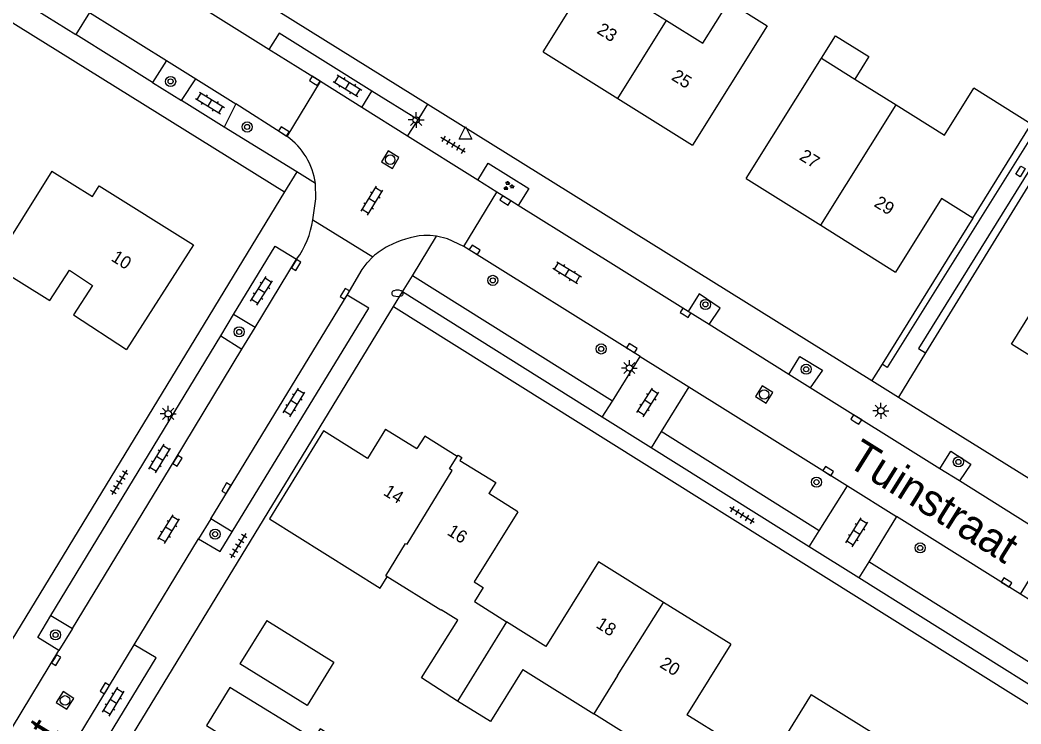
# Model space of a CAD drawing. Extents: x 136000 to 141014, y 402000 to 403500.
# Drawn here: x 137879.3 to 137958.3, y 402207.2 to 402262.7 of the extents above; entities that cross this region are included whole.
import ezdxf

# ---------------------------------------------------------------- set-up
doc = ezdxf.new("R2010")
doc.units = 0
for name, color, linetype in [('gg-afsc-erfafscheiding', 7, 'Continuous'), ('gg-anno-huisnummerreeks BGT', 7, 'Continuous'), ('gg-anno-openbare ruimte label', 7, 'Continuous'), ('gg-bbg-bijgebouw', 7, 'Continuous'), ('gg-bbg-gedigitaliseerde bebouwing', 7, 'Continuous'), ('gg-bbg-gedigitaliseerde bijgebouw', 7, 'Continuous'), ('gg-bbg-hoofdgebouw', 7, 'Continuous'), ('gg-bbg-luifel en loopbrug', 7, 'Continuous'), ('gg-bbg-tussenscheiding', 7, 'Continuous'), ('gg-knt-verharding', 7, 'Continuous'), ('gg-knt-verharding nz', 7, 'Continuous'), ('gt-grn-groengrens', 7, 'Continuous'), ('gt-grn-vlakafsluiter', 7, 'Continuous'), ('gt-grn-weggrens', 7, 'Continuous'), ('gt-symb-boom', 7, 'Continuous'), ('gt-symb-brandkraan', 7, 'Continuous'), ('gt-symb-groenvak', 7, 'Continuous'), ('gt-symb-klinker verharding', 7, 'Continuous'), ('gt-symb-kolk', 7, 'Continuous'), ('gt-symb-kolk center center', 7, 'Continuous'), ('gt-symb-lichtmast', 7, 'Continuous'), ('gt-symb-rioolschacht', 7, 'Continuous'), ('gt-symb-tegel verharding', 7, 'Continuous'), ('gt-symb-waterafsluiter', 7, 'Continuous')]:
    doc.layers.add(name, color=color, linetype=linetype)

# ---------------------------------------------------------------- blocks, each defined once
blk = doc.blocks.new('gt0-KOLKCC')
at = {"layer": 'gt-symb-kolk center center'}
blk.add_lwpolyline([(-0.375, 0.2), (0.375, 0.2), (0.375, -0.2), (-0.375, -0.2)], close=True, dxfattribs=at)
blk = doc.blocks.new('gt0-BOOM')
at = {"layer": 'gt-symb-boom'}
for radius in [0.4, 0.2]:
    blk.add_circle((0, 0), radius, dxfattribs=at)
blk = doc.blocks.new('gt0-KOLK')
at = {"layer": 'gt-symb-kolk'}
blk.add_lwpolyline([(0, 0), (0.375, 0), (0.375, 0.4), (-0.375, 0.4), (-0.375, 0), (0, 0)], dxfattribs=at)
blk = doc.blocks.new('gt0-KL1')
at = {"layer": 'gt-symb-klinker verharding'}
for p, q in [((-1.15, 0.3), (1.15, 0.3)), ((-1, -0.3), (-1, 0.3)), ((-0.5, 0.3), (-0.5, 0.45)), ((0, -0.3), (0, 0.3)), ((0.5, 0.3), (0.5, 0.45)), ((1, -0.3), (1, 0.3)), ((-1.15, -0.3), (1.15, -0.3)), ((-0.5, -0.45), (-0.5, -0.3)), ((0.5, -0.45), (0.5, -0.3))]:
    blk.add_line(p, q, dxfattribs=at)
blk = doc.blocks.new('gt0-LMAST')
at = {"layer": 'gt-symb-lichtmast'}
for p, q in [((-0.182, 0.173), (-0.447, 0.438)), ((-0.005, 0.246), (-0.005, 0.621)), ((0.172, 0.173), (0.437, 0.438)), ((-0.255, -0.004), (-0.63, -0.004)), ((-0.182, -0.181), (-0.447, -0.446)), ((-0.005, -0.254), (-0.005, -0.629)), ((0.437, -0.446), (0.172, -0.181)), ((0.245, -0.004), (0.62, -0.004))]:
    blk.add_line(p, q, dxfattribs=at)
blk.add_circle((-0.005, -0.004), 0.25, dxfattribs=at)
blk = doc.blocks.new('gt0-RS')
at = {"layer": 'gt-symb-rioolschacht'}
blk.add_lwpolyline([(-0.5, -0.5), (0.5, -0.5), (0.5, 0.5), (-0.5, 0.5)], close=True, dxfattribs=at)
blk.add_circle((0, 0), 0.375, dxfattribs=at)
blk = doc.blocks.new('gt0-GRVAK')
at = {"layer": 'gt-symb-groenvak'}
for p, q in [((-0.11, 0.189), (-0.228, 0.24)), ((-0.182, 0.153), (0.088, 0.153)), ((-0.091, 0.211), (-0.156, 0.322)), ((-0.047, 0.214), (-0.047, 0.393)), ((-0.004, 0.211), (0.061, 0.322)), ((0.015, 0.189), (0.133, 0.24)), ((0.262, -0.052), (0.197, 0.059)), ((0.305, -0.049), (0.305, 0.13)), ((0.349, -0.052), (0.414, 0.059)), ((-0.245, -0.228), (-0.363, -0.177)), ((-0.318, -0.264), (-0.047, -0.264)), ((-0.226, -0.206), (-0.291, -0.095)), ((-0.183, -0.203), (-0.183, -0.024)), ((-0.139, -0.206), (-0.074, -0.095)), ((-0.12, -0.228), (-0.002, -0.177)), ((0.243, -0.074), (0.125, -0.023)), ((0.17, -0.11), (0.441, -0.11)), ((0.368, -0.074), (0.486, -0.023))]:
    blk.add_line(p, q, dxfattribs=at)
blk = doc.blocks.new('gt0-TEG1')
at = {"layer": 'gt-symb-tegel verharding'}
for p, q in [((-1.125, 0), (1.125, 0)), ((-0.9, -0.25), (-0.9, 0.25)), ((-0.45, -0.25), (-0.45, 0.25)), ((0, -0.25), (0, 0.25)), ((0.45, -0.25), (0.45, 0.25)), ((0.9, -0.25), (0.9, 0.25))]:
    blk.add_line(p, q, dxfattribs=at)
blk = doc.blocks.new('gt0-BR')
at = {"layer": 'gt-symb-brandkraan'}
for centre, radius, start, end in [((-0.244, 0), 0.206, 107.56694, 252.43307), ((0.599, -2.664), 3, 106.89205, 107.56694), ((0, -0.691), 0.938, 73.10799, 106.89205), ((-0.599, -2.664), 3, 72.43309, 73.10799), ((0.244, 0), 0.206, 287.56695, 72.43309), ((0.599, 2.664), 3, 252.43307, 253.10797), ((0, 0.691), 0.938, 253.10797, 286.89206), ((-0.599, 2.664), 3, 286.89206, 287.56695)]:
    blk.add_arc(centre, radius, start, end, dxfattribs=at)
blk = doc.blocks.new('gt0-WAFSL')
at = {"layer": 'gt-symb-waterafsluiter'}
for p, q in [((-0.5, -0.333), (0, 0.667)), ((0, 0.667), (0.5, -0.333)), ((0.5, -0.333), (-0.5, -0.333))]:
    blk.add_line(p, q, dxfattribs=at)

msp = doc.modelspace()

# ---------------------------------------------------------------- linework, layer by layer
at = {"layer": 'gg-afsc-erfafscheiding'}
for p, q in [((137970.18, 402267.968), (137950.781, 402236.464)), ((137954.521, 402247.088), (137947.358, 402235.568)), ((137947.358, 402235.568), (137946.562, 402234.288))]:
    msp.add_line(p, q, dxfattribs=at)
at = {"layer": 'gg-bbg-bijgebouw'}
msp.add_line((137898.79, 402215.35), (137896.67, 402211.93), dxfattribs=at)
at = {"layer": 'gg-bbg-gedigitaliseerde bebouwing'}
for p, q in [((137936.64, 402250.21), (137942.584, 402259.716)), ((137942.584, 402259.716), (137945.22, 402258.067)), ((137945.22, 402258.067), (137948.476, 402256.03)), ((137935.42, 402213.47), (137931.962, 402207.917)), ((137918.997, 402211.479), (137916.441, 402207.371)), ((137918.997, 402211.479), (137924.599, 402207.987)), ((137913.84, 402208.988), (137911.001, 402210.819)), ((137916.441, 402207.371), (137913.84, 402208.988)), ((137929.718, 402204.801), (137924.599, 402207.987))]:
    msp.add_line(p, q, dxfattribs=at)
for points in [[(137926.492, 402269.65), (137929.309, 402267.891), (137927.26, 402264.61), (137930.358, 402262.676)], [(137930.358, 402262.676), (137933.22, 402260.889), (137935.268, 402264.17), (137938.303, 402262.275), (137932.41, 402252.84)], [(137948.476, 402256.03), (137952.283, 402253.648), (137954.598, 402257.348)], [(137881.82, 402250.8), (137877.182, 402243.383), (137881.657, 402240.582), (137883.235, 402242.989), (137885.049, 402241.781), (137883.528, 402239.461), (137887.71, 402236.72)], [(137933.885, 402204.022), (137935.095, 402205.966), (137931.962, 402207.917)]]:
    msp.add_lwpolyline(points, dxfattribs=at)
at = {"layer": 'gg-bbg-gedigitaliseerde bijgebouw'}
msp.add_lwpolyline([(137898.79, 402215.35), (137904.097, 402212.053), (137901.977, 402208.643), (137896.67, 402211.93)], dxfattribs=at)
at = {"layer": 'gg-bbg-hoofdgebouw'}
for p, q in [((137920.62, 402260.2), (137926.492, 402269.65)), ((137920.62, 402260.2), (137926.515, 402256.52)), ((137959.144, 402254.495), (137954.598, 402257.348)), ((137926.515, 402256.52), (137932.41, 402252.84)), ((137954.521, 402247.088), (137959.144, 402254.495)), ((137936.64, 402250.21), (137942.53, 402246.525)), ((137942.53, 402246.525), (137948.42, 402242.84)), ((137908.17, 402230.44), (137906.734, 402228.13)), ((137908.17, 402230.44), (137910.645, 402228.904)), ((137918.6, 402223.93), (137916.311, 402225.359)), ((137930.11, 402216.776), (137924.98, 402219.97)), ((137935.42, 402213.47), (137930.11, 402216.776)), ((137941.76, 402209.51), (137938.177, 402203.732)), ((137941.76, 402209.51), (137946.911, 402206.306))]:
    msp.add_line(p, q, dxfattribs=at)
for points in [[(137881.82, 402250.8), (137885.04, 402248.79), (137885.57, 402249.63), (137893, 402244.98), (137887.71, 402236.72)], [(137954.521, 402247.088), (137952.045, 402248.637), (137948.42, 402242.84)], [(137962.83, 402233.87), (137957.57, 402237.14), (137961.162, 402242.921)], [(137906.734, 402228.13), (137903.276, 402230.301), (137899.007, 402223.362), (137907.735, 402217.89), (137908.306, 402218.8)], [(137913.827, 402228.288), (137911.269, 402229.896), (137910.645, 402228.904)], [(137913.827, 402228.288), (137913.892, 402228.394), (137914.193, 402228.209), (137914.041, 402227.962), (137916.874, 402226.222), (137916.311, 402225.359)], [(137918.6, 402223.93), (137915.168, 402218.404), (137915.888, 402217.96), (137915.185, 402216.845), (137917.704, 402215.251)], [(137924.98, 402219.97), (137920.814, 402213.283), (137917.704, 402215.251)], [(137911.001, 402210.819), (137913.866, 402215.366), (137912.557, 402216.181), (137912.54, 402216.154), (137908.306, 402218.8)], [(137906.636, 402204.585), (137902.998, 402206.811), (137902.486, 402206.001), (137895.874, 402210.057), (137894.029, 402207.055), (137895.217, 402206.325)]]:
    msp.add_lwpolyline(points, dxfattribs=at)
at = {"layer": 'gg-bbg-luifel en loopbrug'}
msp.add_lwpolyline([(137942.584, 402259.716), (137943.69, 402261.483), (137946.326, 402259.834), (137945.22, 402258.067)], dxfattribs=at)
at = {"layer": 'gg-bbg-tussenscheiding'}
for p, q in [((137926.515, 402256.52), (137930.358, 402262.676)), ((137942.53, 402246.525), (137948.476, 402256.03)), ((137913.223, 402227.304), (137913.827, 402228.288)), ((137926.486, 402211.019), (137930.11, 402216.776)), ((137917.704, 402215.251), (137913.84, 402208.988)), ((137926.486, 402211.019), (137924.599, 402207.987))]:
    msp.add_line(p, q, dxfattribs=at)
for points in [[(137909.749, 402221.432), (137909.869, 402221.358), (137913.417, 402227.183), (137913.223, 402227.304)], [(137908.306, 402218.8), (137908.2, 402218.866), (137909.749, 402221.432)]]:
    msp.add_lwpolyline(points, dxfattribs=at)
at = {"layer": 'gg-knt-verharding'}
for p, q in [((137969.616, 402270.293), (137947.776, 402235.31)), ((137880.664, 402263.472), (137883.718, 402261.571)), ((137898.968, 402260.398), (137893.897, 402263.549)), ((137884.788, 402263.323), (137883.718, 402261.571)), ((137884.788, 402263.323), (137890.89, 402259.52)), ((137902.782, 402258.028), (137898.968, 402260.398)), ((137890.89, 402259.52), (137893.188, 402258.088)), ((137892.075, 402256.369), (137893.188, 402258.088)), ((137893.188, 402258.088), (137896.361, 402256.11)), ((137900.391, 402253.533), (137903.025, 402257.876)), ((137903.025, 402257.876), (137902.782, 402258.028)), ((137906.3, 402255.824), (137903.025, 402257.876)), ((137889.776, 402257.8), (137892.075, 402256.369)), ((137906.3, 402255.824), (137907.097, 402257.116)), ((137910.737, 402254.847), (137907.097, 402257.116)), ((137895.436, 402254.259), (137892.075, 402256.369)), ((137896.361, 402256.11), (137895.436, 402254.259)), ((137900.217, 402253.65), (137896.361, 402256.11)), ((137909.914, 402253.56), (137906.3, 402255.824)), ((137911.507, 402256.086), (137946.562, 402234.288)), ((137909.914, 402253.56), (137910.737, 402254.847)), ((137901.155, 402250.743), (137895.436, 402254.259)), ((137900.391, 402253.533), (137900.217, 402253.65)), ((137915.444, 402250.095), (137909.914, 402253.56)), ((137902.642, 402249.828), (137901.155, 402250.743)), ((137916.958, 402249.147), (137915.444, 402250.095)), ((137900.184, 402249.164), (137826.33, 402128.07)), ((137914.355, 402244.854), (137916.958, 402249.147)), ((137918.05, 402248.463), (137916.958, 402249.147)), ((137918.637, 402248.097), (137918.05, 402248.463)), ((137923.87, 402244.83), (137918.637, 402248.097)), ((137902.422, 402246.962), (137907.172, 402244.041)), ((137910.288, 402242.553), (137912.182, 402245.677)), ((137928.28, 402236.171), (137914.355, 402244.854)), ((137925.538, 402243.79), (137923.87, 402244.83)), ((137932.069, 402239.713), (137925.538, 402243.79)), ((137909.51, 402241.27), (137910.288, 402242.553)), ((137925.273, 402231.392), (137909.51, 402241.27)), ((137840.648, 402128.477), (137908.81, 402240.12)), ((137908.81, 402240.12), (137960.41, 402207.79)), ((137933.708, 402238.691), (137932.069, 402239.713)), ((137895.163, 402237.801), (137896.178, 402239.483)), ((137897.889, 402238.467), (137896.178, 402239.483)), ((137896.833, 402236.754), (137897.889, 402238.467)), ((137940.006, 402234.76), (137933.708, 402238.691)), ((137881.759, 402215.743), (137895.163, 402237.801)), ((137895.163, 402237.801), (137896.833, 402236.754)), ((137926.072, 402232.662), (137928.28, 402236.171)), ((137928.28, 402236.171), (137932.1, 402233.784)), ((137950.781, 402236.464), (137948.665, 402232.977)), ((137947.776, 402235.31), (137947.358, 402235.568)), ((137941.693, 402233.707), (137940.006, 402234.76)), ((137946.562, 402234.288), (137948.665, 402232.977)), ((137932.1, 402233.784), (137929.92, 402230.25)), ((137932.1, 402233.784), (137944.622, 402225.96)), ((137951.934, 402227.316), (137941.693, 402233.707)), ((137925.273, 402231.392), (137926.072, 402232.662)), ((137948.665, 402232.977), (137978.895, 402214.134)), ((137929.132, 402228.974), (137925.273, 402231.392)), ((137929.92, 402230.25), (137929.132, 402228.974)), ((137941.599, 402221.162), (137929.132, 402228.974)), ((137953.474, 402226.355), (137951.934, 402227.316)), ((137959.716, 402222.459), (137953.474, 402226.355)), ((137942.398, 402222.431), (137944.622, 402225.96)), ((137944.622, 402225.96), (137948.49, 402223.543)), ((137894.378, 402223.379), (137893.407, 402221.789)), ((137896.07, 402222.347), (137894.378, 402223.379)), ((137948.49, 402223.543), (137946.31, 402219.979)), ((137958.291, 402217.419), (137948.49, 402223.543)), ((137941.599, 402221.162), (137942.398, 402222.431)), ((137888.33, 402213.439), (137893.407, 402221.789)), ((137958.291, 402217.419), (137960.906, 402221.719)), ((137945.528, 402218.7), (137941.599, 402221.162)), ((137946.31, 402219.979), (137945.528, 402218.7)), ((137962.38, 402208.14), (137945.528, 402218.7)), ((137960.829, 402215.802), (137958.291, 402217.419)), ((137881.759, 402215.743), (137883.452, 402214.721)), ((137883.452, 402214.721), (137882.392, 402212.976)), ((137878.721, 402206.931), (137882.392, 402212.976))]:
    msp.add_line(p, q, dxfattribs=at)
for points in [[(137802.467, 402324.025), (137832.521, 402305.259), (137865.923, 402284.43), (137911.507, 402256.086)], [(137796.264, 402314.159), (137829.568, 402293.147), (137877.981, 402262.977), (137900.184, 402249.164)], [(137989.266, 402298.825), (137988.922, 402299.054), (137950.243, 402236.8), (137950.781, 402236.464)], [(137907.097, 402257.116), (137899.762, 402261.69), (137898.968, 402260.398)], [(137915.444, 402250.095), (137916.266, 402251.432), (137919.471, 402249.425), (137918.637, 402248.097)], [(137902.422, 402246.962), (137902.66, 402248.627), (137902.642, 402249.828)], [(137912.182, 402245.677), (137911.692, 402245.727), (137911.196, 402245.729)], [(137914.355, 402244.854), (137913.063, 402245.465), (137912.182, 402245.677)], [(137896.178, 402239.483), (137899.448, 402244.883), (137901.152, 402243.861)], [(137905.136, 402241.025), (137906.314, 402243.051), (137906.713, 402243.572), (137907.172, 402244.041)], [(137896.07, 402222.347), (137906.847, 402239.988), (137905.136, 402241.025)], [(137933.708, 402238.691), (137934.591, 402239.98), (137932.934, 402241.115), (137932.069, 402239.713)], [(137940.006, 402234.76), (137940.883, 402236.184), (137942.668, 402235.106), (137941.693, 402233.707)], [(137951.934, 402227.316), (137952.778, 402228.719), (137954.381, 402227.669), (137953.474, 402226.355)], [(137893.407, 402221.789), (137895.103, 402220.78), (137896.07, 402222.347)], [(137882.392, 402212.976), (137880.713, 402214.005), (137881.759, 402215.743)], [(137885.273, 402204.547), (137890.058, 402212.405), (137888.33, 402213.439)]]:
    msp.add_lwpolyline(points, dxfattribs=at)
for centre, radius, start, end in [((137897.283, 402249.108), 5.408, 7.65001, 54.91216), ((137895.755, 402247.882), 6.73, 323.31364, 352.14371), ((137911.866, 402238.473), 7.287, 95.27759, 118.54663), ((137910.874, 402239.953), 5.516, 116.83906, 132.16194)]:
    msp.add_arc(centre, radius, start, end, dxfattribs=at)
at = {"layer": 'gg-knt-verharding nz'}
for p, q in [((137897.889, 402238.467), (137901.152, 402243.861)), ((137894.378, 402223.379), (137905.136, 402241.025)), ((137883.549, 402205.541), (137888.33, 402213.439))]:
    msp.add_line(p, q, dxfattribs=at)
msp.add_lwpolyline([(137883.452, 402214.721), (137891.576, 402228.053), (137896.833, 402236.754)], dxfattribs=at)
at = {"layer": 'gt-grn-groengrens'}
for p, q in [((137926.072, 402232.662), (137910.288, 402242.553)), ((137942.398, 402222.431), (137929.92, 402230.25)), ((137962.988, 402209.529), (137946.31, 402219.979))]:
    msp.add_line(p, q, dxfattribs=at)
at = {"layer": 'gt-grn-vlakafsluiter'}
msp.add_line((137890.89, 402259.52), (137889.776, 402257.8), dxfattribs=at)
at = {"layer": 'gt-grn-weggrens'}
for p, q in [((137889.776, 402257.8), (137883.718, 402261.571)), ((137910.737, 402254.847), (137911.507, 402256.086)), ((137901.155, 402250.743), (137900.184, 402249.164)), ((137908.81, 402240.12), (137909.51, 402241.27))]:
    msp.add_line(p, q, dxfattribs=at)

# ---------------------------------------------------------------- block references
at = {"layer": 'gt-symb-boom'}
for p in [(137891.204, 402257.876), (137897.242, 402254.283), (137916.631, 402242.183), (137933.419, 402240.282), (137896.621, 402238.116), (137925.193, 402236.772), (137941.372, 402235.169), (137953.387, 402227.86), (137942.185, 402226.259), (137894.711, 402222.158), (137950.37, 402221.073), (137882.121, 402214.21)]:
    msp.add_blockref('gt0-BOOM', p, dxfattribs=at)
at = {"layer": 'gt-symb-brandkraan'}
msp.add_blockref('gt0-BR', (137909.114, 402241.16), dxfattribs=at)
at = {"layer": 'gt-symb-groenvak'}
msp.add_blockref('gt0-GRVAK', (137917.863, 402249.629), dxfattribs=at)
at = {"layer": 'gt-symb-klinker verharding'}
for p, rotation in [((137905.166, 402257.535), -31.543673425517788), ((137894.313, 402256.18), -31.543673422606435), ((137907.094, 402248.472), 58.32868147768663), ((137922.509, 402242.797), -31.51371626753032), ((137898.377, 402241.349), 57.1683510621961), ((137900.948, 402232.549), 58.53512697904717), ((137928.882, 402232.556), 57.37496440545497), ((137890.346, 402228.122), 58.53512697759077), ((137891.062, 402222.552), 58.53512697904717), ((137945.365, 402222.3), 57.915638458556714), ((137886.686, 402208.946), 58.53512698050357)]:
    msp.add_blockref('gt0-KL1', p, dxfattribs=dict(at, rotation=rotation))
at = {"layer": 'gt-symb-kolk'}
for p, rotation in [((137902.477, 402257.75), -32.0053832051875), ((137900.035, 402253.768), -32.54589339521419), ((137917.519, 402248.327), -32.00538320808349), ((137915.1, 402244.413), -32.0053832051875), ((137900.933, 402243.498), -121.33720572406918), ((137905.136, 402241.025), 58.61387523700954), ((137931.734, 402239.451), -32.0053832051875), ((137927.502, 402236.664), -32.00538320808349), ((137945.223, 402231.033), -32.00538320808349), ((137891.576, 402228.053), -121.33720572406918), ((137943.009, 402226.971), -32.00538320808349), ((137895.774, 402225.676), 58.74151468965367), ((137957.082, 402218.176), -32.00538321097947), ((137882.006, 402212.33), -121.33720572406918), ((137886.19, 402209.893), 58.741514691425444)]:
    msp.add_blockref('gt0-KOLK', p, dxfattribs=dict(at, rotation=rotation))
at = {"layer": 'gt-symb-kolk center center', "rotation": -120.79671391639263}
msp.add_blockref('gt0-KOLKCC', (137958.286, 402250.777), dxfattribs=at)
at = {"layer": 'gt-symb-lichtmast'}
for p in [(137910.588, 402254.839), (137927.422, 402235.269), (137891.02, 402231.661), (137947.273, 402231.897)]:
    msp.add_blockref('gt0-LMAST', p, dxfattribs=at)
at = {"layer": 'gt-symb-rioolschacht'}
for p, rotation in [((137908.537, 402251.704), 59.12470831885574), ((137938.052, 402233.182), -32.00538320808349), ((137882.869, 402209.043), -32.46679945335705)]:
    msp.add_blockref('gt0-RS', p, dxfattribs=dict(at, rotation=rotation))
at = {"layer": 'gt-symb-tegel verharding'}
for p, rotation in [((137913.503, 402252.88), 148.66279427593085), ((137887.155, 402226.257), -121.54367342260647), ((137936.303, 402223.665), 148.66279427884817), ((137896.542, 402221.255), -121.54367342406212)]:
    msp.add_blockref('gt0-TEG1', p, dxfattribs=dict(at, rotation=rotation))
at = {"layer": 'gt-symb-waterafsluiter'}
msp.add_blockref('gt0-WAFSL', (137914.492, 402253.645), dxfattribs=at)

# ---------------------------------------------------------------- texts
at = {"layer": 'gg-anno-huisnummerreeks BGT'}
for s, rotation, p in [('23', 328, (137924.778, 402261.731)), ('25', 328, (137930.668, 402258.054)), ('27', 328, (137940.764, 402251.758)), ('29', 328, (137946.658, 402248.071)), ('10', 327.9, (137886.44, 402243.778)), ('14', 328.2, (137907.926, 402225.295)), ('16', 327.9, (137912.958, 402222.158)), ('18', 328.1, (137924.708, 402214.839)), ('20', 328.1, (137929.742, 402211.705))]:
    msp.add_text(s, height=1, rotation=rotation, dxfattribs=at).set_placement(p)
at = {"layer": 'gg-anno-openbare ruimte label'}
for s, rotation, p in [('Tuinstraat', 328, (137944.467, 402227.649)), ('Hofstraat', 58.7, (137875.44, 402194.992))]:
    msp.add_text(s, height=2.5, rotation=rotation, dxfattribs=at).set_placement(p)

doc.saveas('drawing.dxf')
